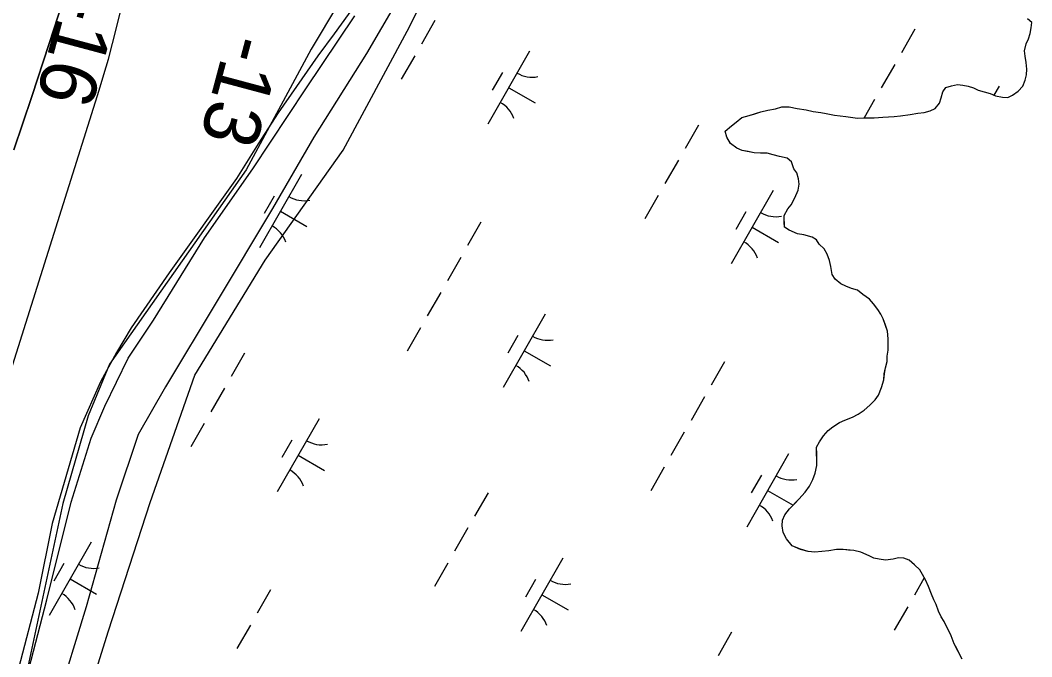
# Model space of a CAD drawing. Extents: x 3930721 to 3950824, y 220441 to 242861.
# Drawn here: x 3942447 to 3943047, y 231514 to 231891 of the extents above; entities that cross this region are included whole.
import ezdxf

# ---------------------------------------------------------------- set-up
doc = ezdxf.new("R2010")
doc.units = 0
for name, color, linetype in [('V-RIVR-EDGE', 7, 'Continuous'), ('V-RIVR-JETY', 7, 'Continuous'), ('V-RIVR-RANG', 7, 'Continuous'), ('V-RRAP-FSHR', 7, 'Continuous'), ('V-TOPO-DPTH', 7, 'Continuous'), ('V-TOPO-MINR', 7, 'Continuous'), ('V-TOPO-SHOR', 7, 'Continuous'), ('V-WETL-SWMP', 7, 'Continuous')]:
    doc.layers.add(name, color=color, linetype=linetype)

msp = doc.modelspace()

# ---------------------------------------------------------------- linework, layer by layer
at = {"layer": 'V-RIVR-EDGE'}
msp.add_lwpolyline([(3942872.3, 232552.97), (3942853.41, 232464.02), (3942817.2, 232330.99), (3942787.28, 232243.61), (3942744.78, 232160.17), (3942743.2, 232130.26), (3942732.18, 232093.27), (3942719.59, 232059.42), (3942692.04, 231997.23), (3942651.89, 231927.96), (3942619.62, 231873.65), (3942581.05, 231802.02), (3942499.97, 231687.09), (3942487.38, 231656.39), (3942472.42, 231604.44), (3942450.38, 231502.11)], dxfattribs=at)
at = {"layer": 'V-RIVR-JETY'}
for points in [[(3942670.2, 231901.39), (3942652.42, 231870.93), (3942621.06, 231821.46), (3942596.72, 231779.14), (3942563.85, 231724.54), (3942533.3, 231673.5), (3942517.06, 231645.42), (3942504.09, 231606.36), (3942486.25, 231543.26), (3942468.74, 231486.06)], [(3942434.98, 231440.89), (3942463, 231547.35), (3942477.36, 231605.3), (3942489.17, 231643.17), (3942497.23, 231662.13), (3942511.1, 231690.58), (3942526.21, 231713.15), (3942556.39, 231761.82), (3942585.08, 231802.61), (3942616.45, 231850.12), (3942645.5, 231893.27)]]:
    msp.add_lwpolyline(points, dxfattribs=at)
at = {"layer": 'V-RRAP-FSHR'}
msp.add_lwpolyline([(3942475.54, 231452.58), (3942499.37, 231528.95), (3942524.22, 231604.99), (3942550.68, 231680.43), (3942592.27, 231748.6), (3942638.59, 231813.81), (3942676.4, 231884.25), (3942712.89, 231955.84), (3942747.77, 232027.77), (3942779.46, 232100.92), (3942807.71, 232175.75), (3942832.6, 232251.78), (3942857.28, 232327.88), (3942881.97, 232403.97), (3942906.23, 232480.2)], dxfattribs=at)
at = {"layer": 'V-TOPO-DPTH'}
msp.add_lwpolyline([(3942706.01, 232766.62), (3942520.88, 232068.19), (3942512.19, 232036.12), (3942503.25, 232004.12), (3942493.94, 231972.23), (3942484.39, 231940.4), (3942474.49, 231908.69), (3942464.38, 231877.04), (3942453.94, 231845.49), (3942443.28, 231814.02)], dxfattribs=at)
at = {"layer": 'V-TOPO-MINR'}
for points in [[(3942443.28, 231814.02), (3942453.94, 231845.49), (3942464.38, 231877.04), (3942474.49, 231908.69), (3942484.39, 231940.4), (3942493.94, 231972.23), (3942503.25, 232004.12), (3942512.19, 232036.12), (3942520.88, 232068.19), (3942706.01, 232766.62)], [(3942411.32, 231587.69), (3942493.88, 231849.38), (3942496.68, 231858.55), (3942499.37, 231867.74), (3942501.89, 231876.99), (3942504.29, 231886.27), (3942636.11, 232415.04), (3942653.61, 232485.21)]]:
    msp.add_lwpolyline(points, dxfattribs=at)
at = {"layer": 'V-TOPO-SHOR'}
for points in [[(3942999.12, 231851.9), (3943002.61, 231852.63), (3943005.76, 231852.32), (3943008.91, 231851.65), (3943012.07, 231850.63), (3943014.88, 231849.26), (3943018.38, 231848.25), (3943021.89, 231847.23), (3943025.05, 231845.87), (3943029.25, 231845.21), (3943032.4, 231844.9), (3943035.18, 231846.32), (3943038.65, 231848.8), (3943041.42, 231851.63), (3943042.78, 231855.14), (3943043.45, 231858.29), (3943043.76, 231861.79), (3943043.37, 231865.63), (3943042.64, 231869.46), (3943042.25, 231872.61), (3943043.26, 231876.81), (3943044.63, 231879.62), (3943045.65, 231882.78), (3943046.31, 231886.28), (3943046.63, 231889.43), (3943044.16, 231891.5)], [(3942923.28, 231644.56), (3942926.04, 231647.73), (3942928.82, 231649.86), (3942932.64, 231652.35), (3942935.77, 231653.77), (3942940.29, 231655.57), (3942943.77, 231657.35), (3942947.24, 231659.83), (3942950.71, 231662.66), (3942953.82, 231665.84), (3942955.89, 231668.66), (3942957.59, 231673.22), (3942958.94, 231677.78), (3942959.25, 231681.28), (3942959.92, 231684.78), (3942960.93, 231688.63), (3942960.9, 231691.78), (3942961.56, 231695.28), (3942961.53, 231698.43), (3942961.49, 231701.92), (3942961.1, 231706.46), (3942959.66, 231710.64), (3942958.58, 231713.77), (3942957.15, 231716.56), (3942955.38, 231719.33), (3942952.89, 231722.81), (3942950.42, 231725.58), (3942946.54, 231728.33), (3942943.38, 231730.75), (3942939.87, 231731.76), (3942936.36, 231733.12), (3942933.55, 231734.49), (3942930.03, 231737.26), (3942928.25, 231740.03), (3942927.5, 231744.92), (3942926.77, 231748.41), (3942925.33, 231752.24), (3942923.55, 231755.36), (3942920.73, 231758.13), (3942918.96, 231760.56), (3942916.49, 231762.28), (3942911.59, 231763.63), (3942907.74, 231764.29), (3942902.82, 231766.34), (3942900.01, 231768.06), (3942899.98, 231771.2), (3942899.94, 231775.05), (3942901.99, 231778.91), (3942904.07, 231781.38), (3942906.12, 231785.6), (3942908.17, 231790.16), (3942908.83, 231793.66), (3942908.46, 231796.8), (3942907.37, 231800.29), (3942905.6, 231802.72), (3942904.16, 231806.9), (3942901.69, 231808.97), (3942897.14, 231809.97), (3942893.28, 231810.98), (3942889.78, 231811.99), (3942885.93, 231811.96), (3942882.08, 231812.27), (3942878.58, 231812.93), (3942875.08, 231813.59), (3942871.92, 231814.96), (3942868.05, 231817.72), (3942865.91, 231821.54), (3942864.83, 231825.02), (3942868.64, 231828.21), (3942871.41, 231830.33), (3942874.88, 231833.16), (3942879.07, 231834.25), (3942882.55, 231835.34), (3942886.03, 231836.42), (3942890.21, 231837.51), (3942894.75, 231838.26), (3942898.58, 231839.35), (3942902.78, 231839.39), (3942907.68, 231838.39), (3942912.93, 231837.74), (3942917.14, 231836.74), (3942921.69, 231836.08), (3942924.84, 231835.42), (3942929.74, 231834.42), (3942936.39, 231833.79), (3942943.39, 231832.81), (3942946.89, 231832.85), (3942953.18, 231832.91), (3942958.42, 231833.31), (3942965.05, 231833.73), (3942968.89, 231834.12), (3942974.48, 231834.87), (3942979.01, 231835.62), (3942982.86, 231836.01), (3942986.34, 231837.09), (3942989.47, 231838.52), (3942991.89, 231841.69), (3942992.9, 231844.84), (3942993.92, 231848.35), (3942995.64, 231850.81), (3942999.12, 231851.9)], [(3943005.36, 231512.22), (3943002.15, 231518.48), (3943000.72, 231521.26), (3942998.93, 231526.14), (3942997.14, 231529.62), (3942994.65, 231534.48), (3942992.87, 231537.26), (3942991.44, 231540.74), (3942990, 231544.58), (3942988.57, 231547.36), (3942987.14, 231550.83), (3942985.35, 231555.36), (3942983.56, 231559.19), (3942981.78, 231562.32), (3942980.36, 231565.1), (3942977.18, 231568.21), (3942974, 231570.98), (3942970.85, 231571.99), (3942967.7, 231572.31), (3942964.56, 231571.58), (3942960.02, 231570.83), (3942956.17, 231571.49), (3942953.02, 231572.16), (3942950.21, 231573.53), (3942945.3, 231575.58), (3942941.09, 231576.58), (3942937.94, 231576.9), (3942934.79, 231577.22), (3942930.95, 231577.18), (3942926.41, 231576.43), (3942922.22, 231576.04), (3942918.03, 231575.65), (3942914.19, 231575.96), (3942909.63, 231577.31), (3942904.71, 231579.36), (3942901.18, 231583.52), (3942899.39, 231587.35), (3942898.65, 231591.18), (3942898.97, 231594.68), (3942900.33, 231597.84), (3942903.09, 231601.37), (3942906.21, 231604.54), (3942908.63, 231607.01), (3942912.43, 231611.25), (3942914.84, 231614.77), (3942916.9, 231618.63), (3942918.26, 231622.49), (3942919.26, 231627.05), (3942919.23, 231630.54), (3942919.19, 231633.68), (3942919.15, 231637.88), (3942920.87, 231641.04), (3942923.28, 231644.56)]]:
    msp.add_lwpolyline(points, dxfattribs=at)
at = {"layer": 'V-WETL-SWMP'}
for p, q in [((3942692.85, 231890.47), (3942684.9, 231876.59)), ((3942977.35, 231885.36), (3942969.4, 231871.48)), ((3942680.92, 231869.65), (3942672.97, 231855.76)), ((3942749.04, 231872.46), (3942724.19, 231829.07)), ((3942965.43, 231864.53), (3942957.47, 231850.65)), ((3942732.91, 231859.81), (3942726.94, 231849.39)), ((3943027.25, 231851.69), (3943024.14, 231846.26)), ((3942736.62, 231850.77), (3942752.24, 231841.82)), ((3942953.5, 231843.71), (3942947.28, 231832.85)), ((3942849.12, 231828.63), (3942841.17, 231814.75)), ((3942837.19, 231807.81), (3942829.24, 231793.92)), ((3942613.85, 231799.25), (3942589, 231755.86)), ((3942597.71, 231786.6), (3942591.75, 231776.18)), ((3942825.26, 231786.98), (3942817.31, 231773.1)), ((3942893.38, 231789.79), (3942868.54, 231746.41)), ((3942601.43, 231777.56), (3942617.05, 231768.61)), ((3942877.25, 231777.14), (3942871.28, 231766.73)), ((3942720.22, 231771.08), (3942712.27, 231757.2)), ((3942880.96, 231768.1), (3942896.58, 231759.16)), ((3942708.29, 231750.26), (3942700.34, 231736.37)), ((3942696.37, 231729.43), (3942688.41, 231715.55)), ((3942758.19, 231716.58), (3942733.34, 231673.2)), ((3942684.44, 231708.6), (3942676.49, 231694.72)), ((3942742.05, 231703.93), (3942736.09, 231693.52)), ((3942580.06, 231693.53), (3942572.11, 231679.65)), ((3942745.77, 231694.89), (3942761.39, 231685.94)), ((3942864.56, 231688.42), (3942856.61, 231674.53)), ((3942568.13, 231672.71), (3942560.18, 231658.82)), ((3942852.63, 231667.59), (3942844.68, 231653.71)), ((3942624.32, 231654.69), (3942599.48, 231611.3)), ((3942556.2, 231651.88), (3942548.25, 231638)), ((3942608.19, 231642.04), (3942602.22, 231631.63)), ((3942840.71, 231646.76), (3942832.76, 231632.88)), ((3942611.9, 231633), (3942627.52, 231624.05)), ((3942902.53, 231633.92), (3942877.68, 231590.53)), ((3942828.78, 231625.94), (3942820.83, 231612.05)), ((3942886.4, 231621.26), (3942880.43, 231610.85)), ((3942890.11, 231612.22), (3942905.24, 231603.56)), ((3942724.4, 231610.87), (3942716.45, 231596.98)), ((3942712.47, 231590.04), (3942704.52, 231576.16)), ((3942489.13, 231581.48), (3942464.28, 231538.09)), ((3942700.54, 231569.21), (3942692.59, 231555.33)), ((3942768.67, 231572.03), (3942743.82, 231528.64)), ((3942472.99, 231568.83), (3942467.03, 231558.41)), ((3942476.71, 231559.79), (3942492.33, 231550.84)), ((3942752.53, 231559.37), (3942746.56, 231548.96)), ((3942982.9, 231560.35), (3942977.1, 231550.21)), ((3942595.5, 231553.31), (3942587.55, 231539.43)), ((3942756.24, 231550.33), (3942771.86, 231541.39)), ((3942973.12, 231543.27), (3942965.17, 231529.39)), ((3942583.57, 231532.49), (3942575.62, 231518.6)), ((3942868.74, 231528.2), (3942860.79, 231514.32))]:
    msp.add_line(p, q, dxfattribs=at)
for points in [[(3942648.15, 231903.56), (3942633.2, 231882.64), (3942623.53, 231869.71), (3942610.88, 231851.38), (3942600.07, 231835.87), (3942588.12, 231817.55), (3942575.27, 231796.89), (3942535.47, 231741.19), (3942512.93, 231708.52), (3942504.21, 231693.97), (3942494.82, 231676.61), (3942482.73, 231649.19), (3942466.04, 231592.55), (3942457.82, 231551.4), (3942434.23, 231462.03)], [(3942875.08, 231813.59), (3942871.92, 231814.96), (3942868.05, 231817.72), (3942865.91, 231821.54), (3942864.83, 231825.02), (3942868.64, 231828.21), (3942871.42, 231830.33), (3942874.88, 231833.16), (3942879.06, 231834.26), (3942886.03, 231836.42), (3942890.22, 231837.51), (3942894.75, 231838.26), (3942898.59, 231839.35), (3942902.78, 231839.39), (3942907.68, 231838.39), (3942912.93, 231837.74), (3942917.14, 231836.74), (3942921.69, 231836.08), (3942924.84, 231835.42), (3942929.74, 231834.42), (3942936.39, 231833.79), (3942943.39, 231832.81), (3942953.18, 231832.91), (3942958.42, 231833.31), (3942965.05, 231833.73), (3942968.89, 231834.12), (3942974.48, 231834.87), (3942979.02, 231835.62), (3942982.86, 231836.01), (3942986.34, 231837.09), (3942989.47, 231838.52), (3942991.89, 231841.69), (3942992.9, 231844.85), (3942993.92, 231848.35), (3942995.64, 231850.81), (3942999.12, 231851.9), (3943002.61, 231852.63), (3943005.76, 231852.32), (3943008.91, 231851.65), (3943012.07, 231850.63), (3943014.88, 231849.26), (3943021.89, 231847.24), (3943025.05, 231845.87), (3943029.25, 231845.21), (3943032.4, 231844.9), (3943035.18, 231846.32), (3943038.65, 231848.8), (3943041.42, 231851.63), (3943042.78, 231855.14), (3943043.45, 231858.29), (3943043.76, 231861.79), (3943043.37, 231865.63), (3943042.64, 231869.46), (3943042.25, 231872.61), (3943043.26, 231876.81), (3943044.63, 231879.62), (3943045.65, 231882.78), (3943046.31, 231886.28), (3943046.63, 231889.43), (3943044.16, 231891.5)], [(3942992.87, 231537.26), (3942991.44, 231540.74), (3942990, 231544.57), (3942988.57, 231547.36), (3942987.14, 231550.84), (3942985.35, 231555.36), (3942983.56, 231559.19), (3942981.78, 231562.32), (3942980.35, 231565.1), (3942977.18, 231568.21), (3942974, 231570.98), (3942970.85, 231571.99), (3942967.7, 231572.31), (3942964.56, 231571.58), (3942960.02, 231570.83), (3942956.17, 231571.49), (3942953.02, 231572.16), (3942950.21, 231573.53), (3942945.3, 231575.58), (3942941.09, 231576.58), (3942934.79, 231577.22), (3942930.95, 231577.18), (3942926.41, 231576.44), (3942918.03, 231575.65), (3942914.19, 231575.96), (3942909.63, 231577.32), (3942904.71, 231579.36), (3942901.18, 231583.52), (3942899.39, 231587.35), (3942898.65, 231591.18), (3942898.97, 231594.68), (3942900.33, 231597.84), (3942903.09, 231601.37), (3942908.63, 231607.01), (3942912.43, 231611.25), (3942914.84, 231614.77), (3942916.9, 231618.63), (3942918.26, 231622.49), (3942919.26, 231627.05), (3942919.15, 231637.88), (3942920.87, 231641.04), (3942923.28, 231644.56), (3942926.04, 231647.74), (3942928.82, 231649.86), (3942932.64, 231652.35), (3942935.77, 231653.77), (3942940.29, 231655.57), (3942943.77, 231657.35), (3942947.24, 231659.83), (3942950.71, 231662.67), (3942953.82, 231665.84), (3942955.89, 231668.66), (3942957.59, 231673.22), (3942958.94, 231677.78), (3942959.26, 231681.28), (3942959.92, 231684.78), (3942960.93, 231688.63), (3942960.9, 231691.78), (3942961.56, 231695.28), (3942961.49, 231701.92), (3942961.1, 231706.46), (3942958.58, 231713.77), (3942957.15, 231716.56), (3942955.38, 231719.33), (3942952.89, 231722.8), (3942950.42, 231725.58), (3942946.55, 231728.33), (3942943.38, 231730.75), (3942939.87, 231731.76), (3942936.36, 231733.12), (3942933.55, 231734.49), (3942930.03, 231737.25), (3942928.25, 231740.03), (3942927.5, 231744.92), (3942926.77, 231748.41), (3942925.33, 231752.24), (3942923.55, 231755.36), (3942920.73, 231758.13), (3942918.96, 231760.56), (3942916.49, 231762.28), (3942911.59, 231763.63), (3942907.73, 231764.29), (3942902.82, 231766.34), (3942900.01, 231768.06), (3942899.94, 231775.05), (3942901.99, 231778.91), (3942904.07, 231781.38), (3942906.12, 231785.6), (3942908.17, 231790.16), (3942908.84, 231793.66), (3942908.45, 231796.8), (3942907.37, 231800.29), (3942905.6, 231802.72), (3942904.16, 231806.9), (3942901.69, 231808.97), (3942897.14, 231809.97), (3942893.28, 231810.98), (3942889.78, 231811.99), (3942885.93, 231811.96), (3942882.08, 231812.27), (3942875.08, 231813.59)], [(3943005.36, 231512.22), (3943000.72, 231521.26), (3942998.93, 231526.14), (3942994.65, 231534.49), (3942992.87, 231537.26)]]:
    msp.add_lwpolyline(points, dxfattribs=at)
for centre, start, end in [((3942750.55, 231874.62), 239.42788, 280.97154), ((3942723.1, 231826.68), 19.42788, 60.97154), ((3942615.36, 231801.41), 239.42788, 280.97154), ((3942894.89, 231791.95), 239.42788, 280.97154), ((3942587.9, 231753.47), 19.42788, 60.97154), ((3942867.44, 231744.01), 19.42788, 60.97154), ((3942759.7, 231718.74), 239.42788, 280.97154), ((3942732.25, 231670.8), 19.42788, 60.97154), ((3942625.83, 231656.85), 239.42788, 280.97154), ((3942598.38, 231608.91), 19.42788, 60.97154), ((3942904.04, 231636.07), 239.42788, 280.97154), ((3942876.59, 231588.14), 19.42788, 60.97154), ((3942490.64, 231583.64), 239.42788, 280.97154), ((3942770.17, 231574.18), 239.42788, 280.97154), ((3942463.19, 231535.7), 19.42788, 60.97154), ((3942742.72, 231526.25), 19.42788, 60.97154)]:
    msp.add_arc(centre, 17.62, start, end, dxfattribs=at)

# ---------------------------------------------------------------- texts
at = {"layer": 'V-RIVR-RANG'}
for s, p in [('-16', (3942473.29, 231908.12)), ('-13', (3942570.37, 231884.05))]:
    msp.add_text(s, height=33.5, rotation=255.02833, dxfattribs=at).set_placement(p)

doc.saveas('drawing.dxf')
